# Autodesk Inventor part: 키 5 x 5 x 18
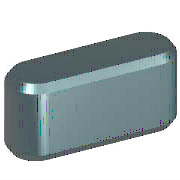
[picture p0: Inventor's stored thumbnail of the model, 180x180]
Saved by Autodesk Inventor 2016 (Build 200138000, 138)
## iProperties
Created: 2012-02
Part Number: 키 5 x 5 x 18
Material: 강철, 연강
Description: 키 및 해당 키홈
Document SubType Name: Modeling
Standard: KS B 1311
Designer: mduedu
Standards Organization: KS
Language: ko-KR
Size Designation: 5 x 5 x 18
Categories: <MemberInstance><Categories><Category DisplayName="샤프트 부품" InternalName="7f7aeb1f-a693-4053-b835-cee3144e0d98" Mnemonic="SHFT"><Category DisplayName="키" Interna
Density: 7.85 g/cm^3
Appearance: 매끄러움 - 노란색
Mass: 4.82049 g
Surface Area: 5.1035 cm^2
Volume: 0.614076 cm^3
IsCustomPart: 1
Author: mduedu
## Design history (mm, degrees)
workplane "Work Plane1"
workplane "Work Plane2"
sketch "스케치1"
  geometry: L1 (2.5, 2.5)-(23.5, 2.5); L2 (23.5, -2.5)-(2.5, -2.5); L3 (0, 8.9)-(0, -4.4) reference; L4 (-5.6, 0)-(33.6, 0) reference; L5 (26, 0)-(26, 7); A1 r 2.5 centre (2.5, 0) between (2.5, 2.5) and (2.5, -2.5); A2 r 2.5 centre (23.5, 0) between (23.5, -2.5) and (23.5, 2.5)
  constraints: 6 end point, 5 point on circle, 4 tangent, 3 point on line, 2 centre point, 1 horizontal, 1 parallel, 1 perpendicular
  dimensions: "d0" = 2.5 radius of A1 (= 0.5 x PB); "d13" = 2.5 radius of A2 (= 0.5 x PB); "d14" = 26 distance between parallel lines of L5 L3 (= NLG)
extrude "본체1" new body sketch "스케치1" taper "d3" = 0 deg; stored distance "d4" = 10
workplane "Work Plane3"
body "Solid1"
chamfer "모따기1" distance "d8" = 0.4 (= PHH); stored, may be unused: second distance "d9" = 0.4 (= PHH), angle "d15" = 45 deg
other parameters: "d1" = -3 (= -PNT), "d2" = 2 (= PH - PNT), "NLG" = 26 [user parameter; used in 3 equation terms], "PB" = 5 [user parameter; used in 2 equation terms], "PNT" = 3 [user parameter; used in 2 equation terms], "PH" = 5 [user parameter; used in 1 equation term], "PHH" = 0.4 [user parameter; used in 2 equation terms], "d10" = 0, "d16" = 0, "d17" = 0, "d18" = 0, "WDMIN" = 12 [user parameter], "PLB2" = 26 (= NLG) [user parameter], "WDMAX" = 17 [user parameter], "PLB1" = 26 (= NLG) [user parameter], "RR" = 0.16 [user parameter], "PUEB" = 2.3 [user parameter]
